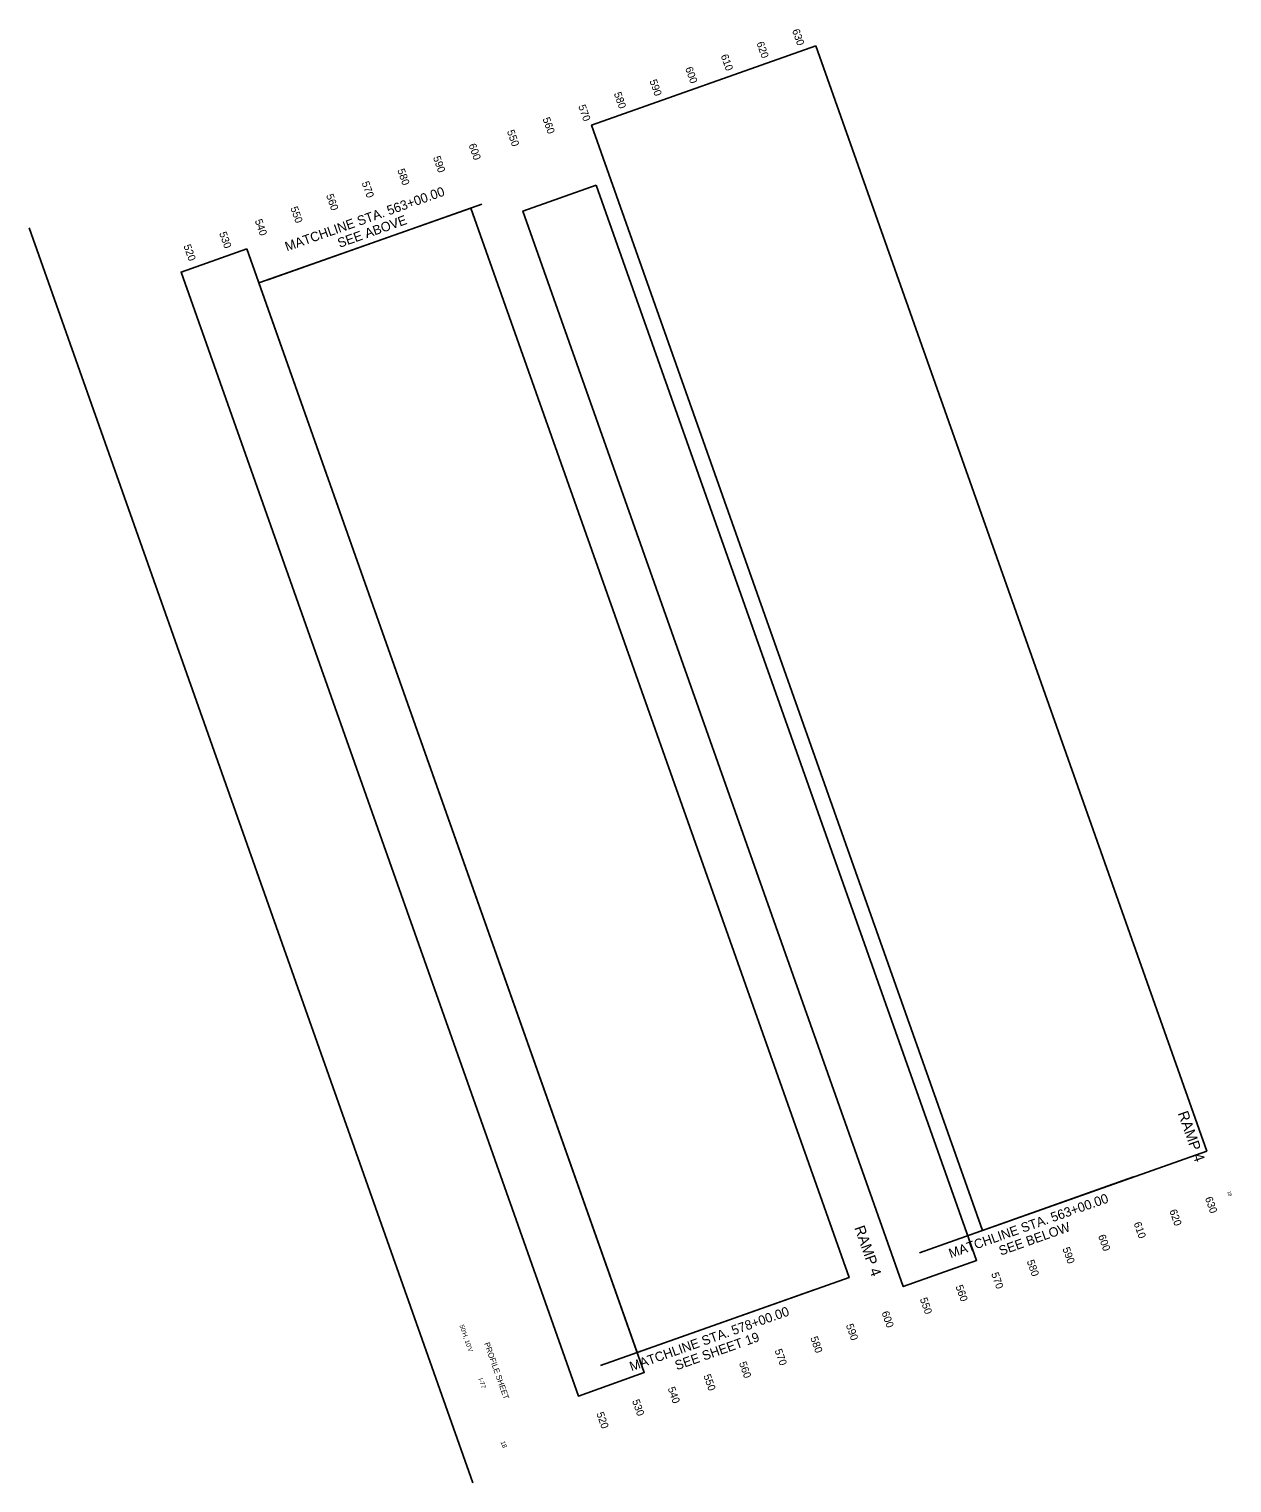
# Model space of a CAD drawing. Extents: x 1985850 to 1991973, y 1123646 to 1127638.
import ezdxf

# ---------------------------------------------------------------- set-up
doc = ezdxf.new("R2010")
doc.units = 0
for name, color, linetype in [('RD_DDB_ElevTX', 7, 'Continuous'), ('RD_SHT_MatchLine', 7, 'Continuous'), ('RD_SHT_ShtClip', 7, 'Continuous'), ('RD_SHT_TX', 7, 'Continuous')]:
    doc.layers.add(name, color=color, linetype=linetype)

msp = doc.modelspace()

# ---------------------------------------------------------------- linework, layer by layer
at = {"layer": 'RD_SHT_MatchLine'}
for p, q in [((1986449.1, 1125336.4), (1986166.2, 1125236.4)), ((1987311, 1124050.3), (1987028.2, 1123950.2)), ((1986888.8, 1123900.9), (1986606, 1123800.9))]:
    msp.add_line(p, q, dxfattribs=at)
at = {"layer": 'RD_SHT_ShtClip'}
for points in [[(1986890.9, 1125545.8), (1987407.8, 1124084.5), (1987111.3, 1123979.6), (1986594.3, 1125440.9)], [(1986600.5, 1125361.6), (1987103.4, 1123939.9), (1987006.4, 1123905.5), (1986503.4, 1125327.3)], [(1986434.5, 1125331.3), (1986934.8, 1123917.2), (1986654.7, 1123818.1), (1986154.4, 1125232.2)], [(1986138.4, 1125277.5), (1986664, 1123791.6), (1986576.9, 1123760.7), (1986051.3, 1125246.7)]]:
    msp.add_lwpolyline(points, close=True, dxfattribs=at)
at = {"layer": 'RD_SHT_TX'}
msp.add_line((1985850.3, 1125305.1), (1986437.3, 1123645.8), dxfattribs=at)

# ---------------------------------------------------------------- texts
at = {"layer": 'RD_DDB_ElevTX'}
for s, p in [('630', (1986859.3, 1125566.1)), ('620', (1986812.2, 1125549.4)), ('610', (1986765, 1125532.7)), ('600', (1986717.9, 1125516)), ('580', (1986623.6, 1125482.7)), ('590', (1986670.7, 1125499.4)), ('570', (1986576.5, 1125466)), ('560', (1986529.3, 1125449.3)), ('550', (1986482.2, 1125432.7)), ('600', (1986431.5, 1125414.7)), ('590', (1986384.4, 1125398.1)), ('580', (1986337.2, 1125381.4)), ('560', (1986243, 1125348)), ('570', (1986290.1, 1125364.7)), ('550', (1986195.8, 1125331.4)), ('540', (1986148.7, 1125314.7)), ('530', (1986101.6, 1125298)), ('520', (1986054.4, 1125281.3)), ('630', (1987405.4, 1124022.3)), ('620', (1987358.3, 1124005.6)), ('610', (1987311.1, 1123989)), ('600', (1987264, 1123972.3)), ('590', (1987216.9, 1123955.6)), ('580', (1987169.7, 1123938.9)), ('560', (1987075.5, 1123905.6)), ('570', (1987122.6, 1123922.3)), ('550', (1987028.3, 1123888.9)), ('600', (1986977.6, 1123871)), ('590', (1986930.5, 1123854.3)), ('580', (1986883.4, 1123837.6)), ('570', (1986836.2, 1123821)), ('560', (1986789.1, 1123804.3)), ('540', (1986694.8, 1123770.9)), ('550', (1986742, 1123787.6)), ('530', (1986647.7, 1123754.3)), ('520', (1986600.5, 1123737.6))]:
    msp.add_text(s, height=10, rotation=289.482, dxfattribs=at).set_placement(p)
at = {"layer": 'RD_SHT_MatchLine'}
for s, p in [('MATCHLINE STA. 563+00.00', (1986191.4, 1125273.9)), ('SEE ABOVE', (1986261, 1125278.6)), ('MATCHLINE STA. 563+00.00', (1987069.3, 1123942.8)), ('SEE BELOW', (1987135.6, 1123946.3)), ('MATCHLINE STA. 578+00.00', (1986647.1, 1123793.4)), ('SEE SHEET 19', (1986707.1, 1123794.7))]:
    msp.add_text(s, height=12.5, rotation=19.482, dxfattribs=at).set_placement(p)
at = {"layer": 'RD_SHT_TX'}
for s, height, p in [('RAMP 4', 14, (1987369.4, 1124134.6)), ('18', 4.5, (1987435, 1124030.9)), ('RAMP 4', 14, (1986941.6, 1123983.2)), ("50'H, 10'V", 6, (1986419.4, 1123853.9)), ('PROFILE SHEET', 7.5, (1986452.1, 1123830.2)), ('I-77', 6, (1986444.4, 1123783.3)), ('18', 6, (1986473.8, 1123700))]:
    msp.add_text(s, height=height, rotation=289.482, dxfattribs=at).set_placement(p)

doc.saveas('drawing.dxf')
